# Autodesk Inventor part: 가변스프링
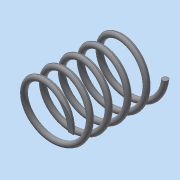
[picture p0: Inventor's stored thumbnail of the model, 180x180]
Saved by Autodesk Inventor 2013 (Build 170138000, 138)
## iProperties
Created: 2017-01
Part Number: 가변스프링
Material: 스테인리스강
Document SubType Name: Modeling
Designer: dgall
Density: 8.08 g/cm^3
Author: dgall
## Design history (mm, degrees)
sketch "스케치1"
  geometry: L1 (20, 0)-(0, 0); L2 (0, 0)-(0, 67.25); L3 (0, 67.25)-(20, 67.25); C1 r 2 at (20, 0); 1 further point
  constraints: 6 end point, 2 coincident, 1 centre point, 1 horizontal, 1 parallel, 1 perpendicular, 1 vertical alignment
  dimensions: "d0" = 40 diameter of L1.start L2; "d2" = 67.25001 distance of L1.end L2.end (derived); "d3" = 4 diameter of C1
feature "코일1" sketch "스케치1" pitch "d4" = 10; turns "d6" = 5; dims "d5" = 67.25001 (= d2), "d7" = 0, angle "d8" = 90 deg, angle "d9" = 90 deg, "d10" = 0, "d11" = 0
node "작업 평면2"
  node "작업 평면1"
feature "분할1"
feature "분할2"
node "솔리드1"
other parameters: "d12" = 0
